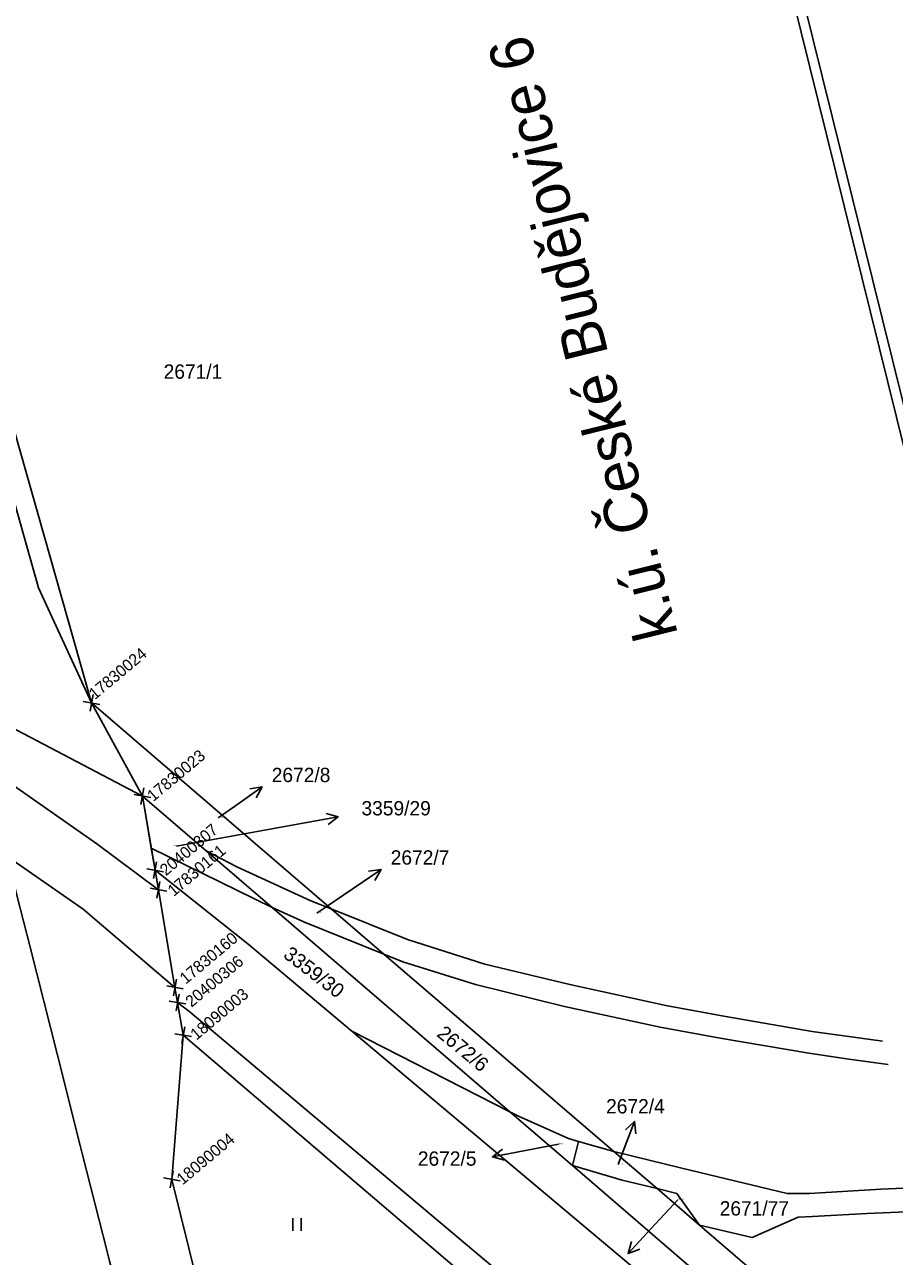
# Model space of a CAD drawing. Extents: x -754679 to -754173, y -1169241 to -1168288.
# Drawn here: x -754507.9 to -754430.6, y -1168501.5 to -1168391.9 of the extents above; entities that cross this region are included whole.
import ezdxf

# ---------------------------------------------------------------- set-up
doc = ezdxf.new("R2010")
doc.units = 0
for name, color, linetype in [('Vrstva 1', 7, 'Continuous'), ('Vrstva 16', 7, 'Continuous'), ('Vrstva 18', 7, 'Continuous'), ('Vrstva 2', 7, 'Continuous'), ('Vrstva 24', 7, 'Continuous'), ('Vrstva 25', 7, 'Continuous'), ('Vrstva 4', 7, 'Continuous'), ('Vrstva 52', 7, 'Continuous'), ('Vrstva 53', 7, 'Continuous'), ('Vrstva 60', 7, 'Continuous')]:
    doc.layers.add(name, color=color, linetype=linetype)

msp = doc.modelspace()

# ---------------------------------------------------------------- linework, layer by layer
at = {"layer": 'Vrstva 1'}
for p, q in [((-754506.68, -1168442.02), (-754517.96, -1168402.36)), ((-754501.97, -1168452.25), (-754516.22, -1168402.04)), ((-754506.68, -1168442.02), (-754501.97, -1168452.25)), ((-754517.36, -1168450.11), (-754497.45, -1168460.53)), ((-754501.97, -1168452.25), (-754497.45, -1168460.53)), ((-754480.66, -1168470.56), (-754501.97, -1168452.25)), ((-754496.66, -1168465.16), (-754497.45, -1168460.53)), ((-754497.45, -1168460.53), (-754491.78, -1168465.4)), ((-754496.32, -1168467.13), (-754496.66, -1168465.16)), ((-754496.66, -1168465.16), (-754485.92, -1168470.44)), ((-754489.05, -1168466.81), (-754491.78, -1168465.4)), ((-754491.78, -1168465.4), (-754485.92, -1168470.44)), ((-754496.32, -1168467.13), (-754496.03, -1168468.86)), ((-754488.07, -1168473.66), (-754496.32, -1168467.13)), ((-754482.46, -1168469.84), (-754489.05, -1168466.81)), ((-754496.03, -1168468.86), (-754494.55, -1168477.55)), ((-754485.92, -1168470.44), (-754483.05, -1168471.75)), ((-754464.78, -1168488.62), (-754485.92, -1168470.44)), ((-754482.46, -1168469.84), (-754480.66, -1168470.56)), ((-754475.99, -1168474.58), (-754480.66, -1168470.56)), ((-754480.66, -1168470.56), (-754473.87, -1168473.28)), ((-754483.05, -1168471.75), (-754475.99, -1168474.58)), ((-754478.83, -1168481.43), (-754488.07, -1168473.66)), ((-754473.87, -1168473.28), (-754467, -1168475.47)), ((-754455.54, -1168492.15), (-754475.99, -1168474.58)), ((-754475.99, -1168474.58), (-754474.28, -1168475.26)), ((-754474.28, -1168475.26), (-754467.84, -1168477.28)), ((-754459.45, -1168477.29), (-754467, -1168475.47)), ((-754467.84, -1168477.28), (-754459.92, -1168479.25)), ((-754450.91, -1168479.15), (-754459.45, -1168477.29)), ((-754494.55, -1168477.55), (-754494.32, -1168478.89)), ((-754494.32, -1168478.89), (-754493.82, -1168481.8)), ((-754459.92, -1168479.25), (-754451.42, -1168481.08)), ((-754445.75, -1168480.12), (-754450.91, -1168479.15)), ((-754437.89, -1168481.48), (-754445.75, -1168480.12)), ((-754464.78, -1168488.62), (-754478.83, -1168481.43)), ((-754474, -1168485.49), (-754478.83, -1168481.43)), ((-754451.42, -1168481.08), (-754446.07, -1168482.05)), ((-754434.43, -1168481.95), (-754437.89, -1168481.48)), ((-754493.82, -1168481.8), (-754494.84, -1168494.63)), ((-754493.82, -1168481.8), (-754451.31, -1168518.1)), ((-754446.07, -1168482.05), (-754438.18, -1168483.39)), ((-754431.64, -1168482.33), (-754434.43, -1168481.95)), ((-754438.18, -1168483.39), (-754434.64, -1168483.94)), ((-754434.64, -1168483.94), (-754431.13, -1168484.4)), ((-754450.1, -1168505.56), (-754474, -1168485.49)), ((-754459.22, -1168493.4), (-754464.78, -1168488.62)), ((-754464.78, -1168488.62), (-754464, -1168489.01)), ((-754464, -1168489.01), (-754459.55, -1168491)), ((-754459.55, -1168491), (-754458.66, -1168491.26)), ((-754458.66, -1168491.26), (-754459.22, -1168493.4)), ((-754458.66, -1168491.26), (-754455.54, -1168492.15)), ((-754451.69, -1168495.45), (-754455.54, -1168492.15)), ((-754455.54, -1168492.15), (-754449.48, -1168493.64)), ((-754459.22, -1168493.4), (-754454.78, -1168494.69)), ((-754425.77, -1168522.16), (-754459.22, -1168493.4)), ((-754449.48, -1168493.64), (-754440.12, -1168495.87)), ((-754494.84, -1168494.63), (-754483.21, -1168541.23)), ((-754454.78, -1168494.69), (-754451.69, -1168495.45)), ((-754449.92, -1168495.89), (-754451.69, -1168495.45)), ((-754447.92, -1168498.69), (-754451.69, -1168495.45)), ((-754447.92, -1168498.69), (-754449.92, -1168495.89)), ((-754440.12, -1168495.87), (-754438.15, -1168495.88)), ((-754438.15, -1168495.88), (-754431.8, -1168495.5)), ((-754431.8, -1168495.5), (-754428.42, -1168495.34)), ((-754439.15, -1168497.98), (-754443.24, -1168499.78)), ((-754437.86, -1168497.94), (-754439.15, -1168497.98)), ((-754433, -1168497.67), (-754437.86, -1168497.94)), ((-754428.18, -1168497.46), (-754433, -1168497.67)), ((-754443.24, -1168499.78), (-754447.92, -1168498.69)), ((-754424.94, -1168518.44), (-754447.92, -1168498.69))]:
    msp.add_line(p, q, dxfattribs=at)
msp.add_lwpolyline([(-754498.39, -1168509.75), (-754500.09, -1168503), (-754500.37, -1168501.89), (-754500.59, -1168501.05), (-754502.8, -1168492.33), (-754502.98, -1168491.62), (-754505.01, -1168483.59), (-754507.47, -1168473.86), (-754508.58, -1168469.47), (-754510.81, -1168460.63), (-754513.14, -1168451.47)], dxfattribs=at)
at = {"layer": 'Vrstva 16'}
for p, q in [((-754486.8, -1168459.72), (-754489.25, -1168461.45)), ((-754490.7, -1168462.48), (-754489.25, -1168461.45)), ((-754494.41, -1168464.98), (-754483, -1168462.92)), ((-754480.05, -1168462.39), (-754483, -1168462.92)), ((-754476.23, -1168467.06), (-754478.71, -1168468.75)), ((-754481.95, -1168470.96), (-754478.71, -1168468.75)), ((-754453.69, -1168489.47), (-754454.76, -1168492.27)), ((-754460.46, -1168491.5), (-754463.38, -1168492.06)), ((-754466.33, -1168492.63), (-754463.38, -1168492.06)), ((-754455.16, -1168493.3), (-754454.76, -1168492.27)), ((-754449.84, -1168496.45), (-754452.23, -1168499.03)), ((-754454.27, -1168501.23), (-754452.23, -1168499.03))]:
    msp.add_line(p, q, dxfattribs=at)
for points in [[(-754487.91, -1168459.89), (-754486.8, -1168459.72), (-754487.33, -1168460.7)], [(-754481.12, -1168462.07), (-754480.05, -1168462.39), (-754480.94, -1168463.06)], [(-754477.34, -1168467.21), (-754476.23, -1168467.06), (-754476.78, -1168468.03)], [(-754454.51, -1168490.22), (-754453.69, -1168489.47), (-754453.58, -1168490.58)], [(-754465.25, -1168492.93), (-754466.33, -1168492.63), (-754465.44, -1168491.95)], [(-754453.22, -1168500.84), (-754454.27, -1168501.23), (-754453.95, -1168500.16)]]:
    msp.add_lwpolyline(points, dxfattribs=at)
at = {"layer": 'Vrstva 2'}
for p, q in [((-754413.4, -1168495.63), (-754457.03, -1168319.17)), ((-754443.29, -1168371.08), (-754428.02, -1168432.82))]:
    msp.add_line(p, q, dxfattribs=at)
at = {"layer": 'Vrstva 25'}
for p, q in [((-754484.07, -1168499.21), (-754484.07, -1168498.08)), ((-754483.32, -1168499.21), (-754483.32, -1168498.08))]:
    msp.add_line(p, q, dxfattribs=at)
at = {"layer": 'Vrstva 4'}
for p, q in [((-754516.61, -1168454.2), (-754501.51, -1168464.78)), ((-754502.71, -1168470.6), (-754517.48, -1168460.34)), ((-754501.51, -1168464.78), (-754496.03, -1168468.86)), ((-754502.71, -1168470.6), (-754494.55, -1168477.55)), ((-754493.21, -1168479.76), (-754494.32, -1168478.89)), ((-754459.9, -1168507.75), (-754493.21, -1168479.76))]:
    msp.add_line(p, q, dxfattribs=at)
at = {"layer": 'Vrstva 53'}
for p, q in [((-754516.22, -1168402.04), (-754501.97, -1168452.25)), ((-754501.97, -1168452.25), (-754497.45, -1168460.53)), ((-754497.45, -1168460.53), (-754496.32, -1168467.13)), ((-754496.32, -1168467.13), (-754496.03, -1168468.86)), ((-754496.03, -1168468.86), (-754494.55, -1168477.55)), ((-754494.55, -1168477.55), (-754494.32, -1168478.89)), ((-754494.32, -1168478.89), (-754493.82, -1168481.8)), ((-754493.82, -1168481.8), (-754494.84, -1168494.63)), ((-754494.84, -1168494.63), (-754483.21, -1168541.23))]:
    msp.add_line(p, q, dxfattribs=at)
at = {"layer": 'Vrstva 60'}
for p, q in [((-754501.84, -1168451.51), (-754502.1, -1168452.99)), ((-754502.71, -1168452.12), (-754501.23, -1168452.38)), ((-754498.19, -1168460.4), (-754496.71, -1168460.66)), ((-754497.32, -1168459.79), (-754497.58, -1168461.27)), ((-754497.06, -1168467), (-754495.58, -1168467.26)), ((-754496.19, -1168466.39), (-754496.45, -1168467.87)), ((-754495.9, -1168468.12), (-754496.16, -1168469.6)), ((-754496.77, -1168468.73), (-754495.29, -1168468.99)), ((-754494.42, -1168476.81), (-754494.68, -1168478.29)), ((-754495.29, -1168477.42), (-754493.81, -1168477.68)), ((-754494.19, -1168478.15), (-754494.45, -1168479.63)), ((-754495.06, -1168478.76), (-754493.58, -1168479.02)), ((-754494.56, -1168481.67), (-754493.08, -1168481.93)), ((-754493.69, -1168481.06), (-754493.95, -1168482.54)), ((-754495.58, -1168494.5), (-754494.1, -1168494.76)), ((-754494.71, -1168493.89), (-754494.97, -1168495.37))]:
    msp.add_line(p, q, dxfattribs=at)

# ---------------------------------------------------------------- texts
at = {"layer": 'Vrstva 16'}
for s, p in [('2672/8', (-754485.95, -1168459.29)), ('3359/29', (-754477.97, -1168462.25)), ('2672/7', (-754475.37, -1168466.63)), ('2672/4', (-754456.22, -1168488.76)), ('2672/5', (-754472.96, -1168493.41))]:
    msp.add_text(s, height=1.275, rotation=360, dxfattribs=at).set_placement(p)
at = {"layer": 'Vrstva 18'}
for s, rotation, p in [('2671/1', 360, (-754495.56, -1168423.41)), ('3359/30', 322.3461, (-754485.01, -1168474.81)), ('2672/6', 320.398, (-754471.36, -1168481.82)), ('2671/77', 360, (-754446.12, -1168497.84))]:
    msp.add_text(s, height=1.275, rotation=rotation, dxfattribs=at).set_placement(p)
for s, p in [('2672/8', (-754490.69, -1168462.48)), ('3359/29', (-754494.71, -1168464.98)), ('2672/7', (-754481.94, -1168470.96)), ('2672/5', (-754460.45, -1168491.5)), ('2672/4', (-754455.15, -1168493.3)), ('2671/78', (-754449.83, -1168496.45))]:
    msp.add_text(s, height=0.1, dxfattribs=at).set_placement(p)
at = {"layer": 'Vrstva 2'}
msp.add_text(' 17830024', height=1.037, rotation=40, dxfattribs=at).set_placement((-754501.97, -1168452.25))
at = {"layer": 'Vrstva 24'}
msp.add_text('k.ú. České Budějovice 6', height=3.84, rotation=103.8896, dxfattribs=at).set_placement((-754449.83, -1168446.12))
at = {"layer": 'Vrstva 52'}
for s, p in [(' 17830023', (-754496.78, -1168461.32)), (' 20400307', (-754495.65, -1168467.92)), (' 17830161', (-754494.96, -1168469.76)), (' 17830160', (-754493.89, -1168477.56)), (' 20400306', (-754493.38, -1168479.62)), (' 18090003', (-754492.94, -1168482.54)), (' 18090004', (-754494.17, -1168495.42))]:
    msp.add_text(s, height=1.037, rotation=40, dxfattribs=at).set_placement(p)

doc.saveas('drawing.dxf')
